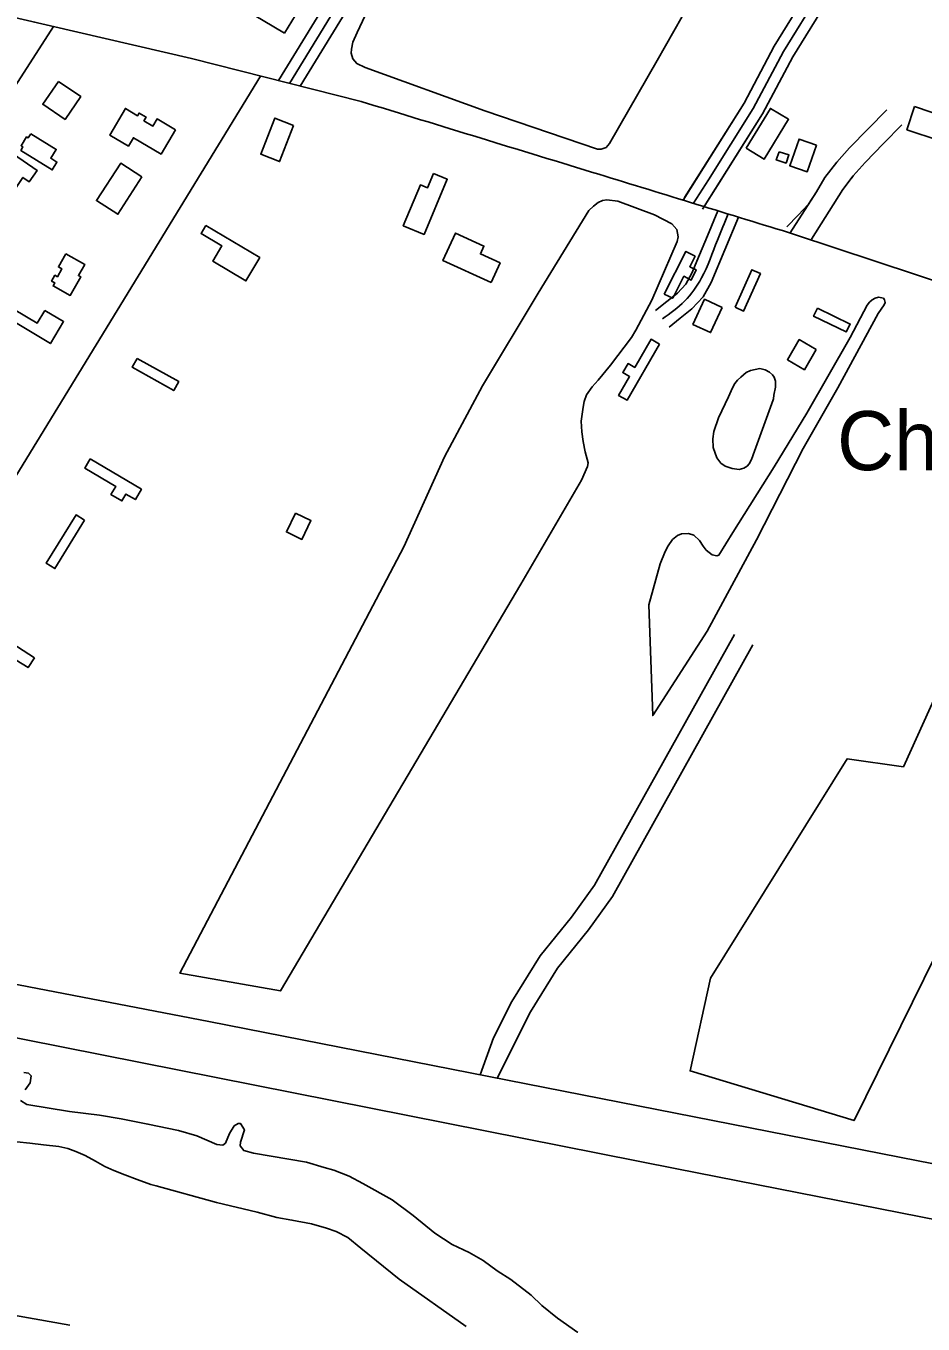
# Model space of a CAD drawing. Extents: x 3855477 to 3893699, y 299188 to 325115.
# Drawn here: x 3865905 to 3867166, y 308321 to 310145 of the extents above; entities that cross this region are included whole.
import ezdxf

# ---------------------------------------------------------------- set-up
doc = ezdxf.new("R2010")
doc.units = 0
for name, color, linetype in [('V-BLDG-OTLN', 7, 'Continuous'), ('V-LEVE-TOET', 7, 'Continuous'), ('V-ROAD-CNTR', 7, 'Continuous'), ('V-SITE-OTLN-IDEN', 7, 'Continuous'), ('V-SITE-VEGE', 7, 'Continuous'), ('V-TOPO-SHOR', 7, 'Continuous')]:
    doc.layers.add(name, color=color, linetype=linetype)

msp = doc.modelspace()

# ---------------------------------------------------------------- linework, layer by layer
at = {"layer": 'V-BLDG-OTLN'}
for points in [[(3866269.1, 310134.6), (3866211.3, 310168.9), (3866230.3, 310200.8), (3866253.5, 310187), (3866249.8, 310180.7), (3866284.3, 310160.2)], [(3865951.1, 310067), (3865982.5, 310045.7), (3865960.6, 310013.5), (3865929.2, 310034.8)], [(3866115.6, 309999.1), (3866095.5, 309964.9), (3866056.6, 309987.8), (3866049.6, 309976), (3866023.2, 309991.6), (3866045.2, 310028.9), (3866062.4, 310018.8), (3866064.5, 310022.5), (3866074.3, 310016.7), (3866071.3, 310011.7), (3866084, 310004.2), (3866089.9, 310014.3)], [(3866917.8, 309973), (3866952, 310029.1), (3866977.4, 310013.7), (3866943.1, 309957.5)], [(3867154.5, 310031.6), (3867199.9, 310016.4), (3867189, 309984), (3867143.7, 309999.1)], [(3866281.4, 310005.1), (3866261.9, 309954.3), (3866235.5, 309964.5), (3866255.1, 310015.3)], [(3865912.3, 309993.5), (3865948, 309971.3), (3865940.3, 309958.9), (3865949.1, 309953.5), (3865942.4, 309942.7), (3865898.3, 309970), (3865901.3, 309974.9), (3865898.7, 309976.5), (3865906.4, 309988.9), (3865908.6, 309987.6)], [(3867016.7, 309977.4), (3867003.6, 309939.9), (3866979, 309948.5), (3866992.1, 309985.9)], [(3865888.2, 309964.5), (3865921.2, 309942), (3865910.2, 309925.9), (3865901.2, 309932), (3865889.7, 309915.1), (3865865.7, 309931.5)], [(3866964, 309968.1), (3866977.8, 309963.6), (3866974, 309952.1), (3866960.2, 309956.6)], [(3866068.6, 309932.8), (3866034.8, 309880.2), (3866004.6, 309899.6), (3866038.8, 309952)], [(3866478.4, 309937.6), (3866497.7, 309929.5), (3866465, 309851.9), (3866435.9, 309864.2), (3866460, 309921.5), (3866469.8, 309917.3)], [(3866158.4, 309864.5), (3866234.2, 309819.4), (3866214.7, 309786.6), (3866168.2, 309814.3), (3866181, 309835.7), (3866151.7, 309853.2)], [(3866559.3, 309784.4), (3866491.6, 309815.3), (3866509.2, 309853.9), (3866549.3, 309835.6), (3866544.3, 309824.6), (3866571.9, 309812)], [(3865961.4, 309824.9), (3865988.1, 309809.9), (3865979.3, 309794.1), (3865982.4, 309792.4), (3865967.7, 309766.2), (3865943.7, 309779.6), (3865946.1, 309783.9), (3865941.6, 309786.5), (3865946.1, 309794.6), (3865949.7, 309792.6), (3865955.9, 309803.7), (3865951.1, 309806.4)], [(3866802.7, 309768.2), (3866833.1, 309828), (3866846.1, 309821.3), (3866838.6, 309806.6), (3866847.7, 309802), (3866840.6, 309787.9), (3866830.3, 309793.2), (3866814.6, 309762.2)], [(3866902.2, 309749.7), (3866925.7, 309802.4), (3866937.9, 309797), (3866914.3, 309744.2)], [(3866884, 309749.5), (3866867.8, 309714.1), (3866843, 309725.4), (3866859.3, 309760.8)], [(3865932, 309745.3), (3865958.3, 309729.6), (3865939.9, 309698.7), (3865881.2, 309733.7), (3865888.9, 309746.5), (3865921.2, 309727.2)], [(3867018, 309748.3), (3867064, 309726.1), (3867058.6, 309714.9), (3867012.6, 309737.1)], [(3866796, 309697.9), (3866750.4, 309618.9), (3866738.6, 309625.7), (3866753.9, 309652.3), (3866744.4, 309657.8), (3866751.8, 309670.6), (3866761.2, 309665.1), (3866784.1, 309704.7)], [(3867016.2, 309690.2), (3866999.6, 309661.9), (3866975.8, 309675.9), (3866992.4, 309704.2)], [(3866061.8, 309677.8), (3866120.3, 309645.1), (3866113.3, 309632.6), (3866054.8, 309665.3)], [(3865995.7, 309536.6), (3866067.9, 309493.9), (3866059.3, 309479.3), (3866046.1, 309487.1), (3866040.4, 309477.5), (3866025, 309486.6), (3866031.7, 309497.9), (3865988.1, 309523.7)], [(3866284.2, 309460.3), (3866271.5, 309433.9), (3866293.3, 309423.5), (3866306, 309449.9)], [(3865987.8, 309450.4), (3865946.1, 309382.5), (3865934.1, 309389.9), (3865975.9, 309457.8)], [(3865917.3, 309257.2), (3865862.5, 309292), (3865854.1, 309278.8), (3865879.1, 309262.9), (3865872.4, 309252.3), (3865885.5, 309244), (3865891.8, 309253.9), (3865908.5, 309243.3)]]:
    msp.add_lwpolyline(points, close=True, dxfattribs=at)
at = {"layer": 'V-LEVE-TOET'}
msp.add_lwpolyline([(3865816.5, 308346.2), (3865967, 308319.4)], dxfattribs=at)
at = {"layer": 'V-ROAD-CNTR'}
for points in [[(3866703.7, 310794), (3866565.5, 310565.8), (3866260.5, 310068.1)], [(3866716.6, 310786.2), (3866578.3, 310558), (3866275.7, 310064.2)], [(3866729.4, 310778.5), (3866591.1, 310550.2), (3866290.9, 310060.4)], [(3864154.9, 310565.8), (3864820.2, 310410.7), (3865696.9, 310201.7), (3866138.4, 310098.9), (3866376.7, 310038.7)], [(3866829.2, 309900.1), (3866914.9, 310036.6), (3866957.4, 310116.3), (3867008.4, 310199.3), (3867046.6, 310270.2), (3867079.2, 310353.6), (3867100.3, 310400.3), (3867137.6, 310467.8)], [(3866831, 309903.8), (3866852.3, 309936.9), (3866914.9, 310036.6), (3866957.4, 310116.3), (3867008.4, 310199.3), (3867046.6, 310270.2), (3867079.2, 310353.6), (3867100.3, 310400.3), (3867137.6, 310467.8)], [(3866843.7, 309895.7), (3866865, 309928.8), (3866927.8, 310029), (3866970.4, 310108.9), (3867021.4, 310191.9), (3867060.2, 310263.9), (3867093, 310347.8), (3867113.7, 310393.6), (3867150.8, 310460.6)], [(3866856.3, 309887.6), (3866877.6, 309920.8), (3866940.8, 310021.5), (3866983.4, 310101.4), (3867034.4, 310184.4), (3867073.8, 310257.6), (3867106.8, 310341.9), (3867127.2, 310386.8), (3867163.9, 310453.3)], [(3866858.9, 309891), (3866940.8, 310021.5), (3866983.4, 310101.4), (3867034.4, 310184.4), (3867073.8, 310257.6), (3867106.8, 310341.9), (3867127.2, 310386.8), (3867163.9, 310453.3)], [(3865944, 310144.2), (3865650.3, 309687.9), (3865194.3, 308971), (3865175.1, 308936.2), (3865158.2, 308867.3)], [(3865487.5, 308802.7), (3865506.7, 308872.4), (3865527, 308916.8), (3865605.7, 309046.7), (3866235.2, 310074.5)], [(3866975.1, 309862.4), (3866990.8, 309878.9), (3867005.6, 309894.4), (3867016.9, 309911.8), (3867028.5, 309932.1), (3867045.3, 309953.6), (3867063, 309973.6), (3867089.3, 310000.5), (3867115.3, 310027.1)], [(3866979.5, 309854), (3867016.9, 309911.8), (3867028.5, 309932.1), (3867045.3, 309953.6), (3867063, 309973.6), (3867089.3, 310000.5), (3867115.3, 310027.1)], [(3867009.2, 309899.9), (3867016.9, 309911.8), (3867028.5, 309932.1), (3867045.3, 309953.6), (3867063, 309973.6), (3867089.3, 310000.5), (3867115.3, 310027.1)], [(3867009.8, 309845.2), (3867053.5, 309915.3), (3867068.4, 309934.5), (3867084.9, 309953.2), (3867110.7, 309979.5), (3867136.7, 310006.1)], [(3867066.2, 309931.6), (3867068.4, 309934.5), (3867084.9, 309953.2), (3867110.7, 309979.5), (3867136.7, 310006.1)], [(3866878.1, 309885.1), (3866863.5, 309849.8), (3866852.4, 309823.2), (3866841.6, 309797.4), (3866833, 309782.1), (3866821.1, 309769.5), (3866806.2, 309757.5), (3866790.6, 309744.9)], [(3866907.2, 309876.2), (3866868.6, 309784.2), (3866857.3, 309764.2), (3866841.5, 309747.4), (3866825.1, 309734.2), (3866809.4, 309721.6)], [(3866985.9, 309852), (3867729.6, 309606.1), (3868057.1, 309502.7)], [(3860983.7, 309748.8), (3862185, 309519.4), (3863555.5, 309254), (3864992.1, 308971.5), (3866162.7, 308746.1), (3867159.7, 308550.2), (3867954.5, 308395.7), (3868105, 308368.9)], [(3860884.4, 309700.6), (3862044.8, 309470.5), (3862858.2, 309310.5), (3864777.9, 308942), (3865687.7, 308763.4), (3866820.3, 308539.2), (3867789.8, 308348.3), (3868065.6, 308297.8)], [(3866544, 308671.2), (3866562.8, 308723.4), (3866588.4, 308774.2), (3866628.3, 308838.4), (3866672.2, 308892.9), (3866704.8, 308937.9), (3866901.2, 309289.8)], [(3866567.7, 308666.5), (3866614.6, 308759.5), (3866652.8, 308821), (3866696, 308874.7), (3866730.1, 308921.8), (3866927.4, 309275.1)]]:
    msp.add_lwpolyline(points, dxfattribs=at)
for points in [[(3866376.7, 310038.7), (3866710.8, 309936.4), (3866985.9, 309852)], [(3866892.5, 309880.7), (3866877.4, 309844.1), (3866855.1, 309790.8), (3866831.3, 309758.4), (3866800, 309733.2)]]:
    msp.add_spline(points, degree=3, dxfattribs=at)
at = {"layer": 'V-SITE-VEGE'}
msp.add_lwpolyline([(3866886.5, 310261.7), (3866792.7, 310096.2), (3866725.7, 309979.9), (3866720.8, 309974), (3866714.2, 309971.6), (3866708.9, 309971.7), (3866550.6, 310025.5), (3866382.3, 310086.5), (3866370.4, 310092), (3866365.1, 310098.7), (3866362.8, 310106.4), (3866362.9, 310112.4), (3866364.8, 310121.9), (3866370.9, 310135.6), (3866419.9, 310239.6)], dxfattribs=at)
for points in [[(3866601, 309360.8), (3866263.5, 308789), (3866122, 308813.8), (3866436.7, 309412.8), (3866493.7, 309539.4), (3866547.4, 309639.1), (3866625.3, 309769.6), (3866696.5, 309885.8), (3866703.2, 309891.7), (3866709.8, 309897), (3866715.8, 309899.4), (3866721.8, 309900.5), (3866737.3, 309898.5), (3866789, 309879.4), (3866813.4, 309866.6), (3866820.4, 309858.8), (3866822.1, 309848.6), (3866820.8, 309842), (3866785.3, 309759.4), (3866762.7, 309717.3), (3866756.6, 309707.2), (3866726.9, 309668.1), (3866709.9, 309647.4), (3866701.5, 309638), (3866693.6, 309626.7), (3866689.9, 309617.2), (3866688.6, 309609.4), (3866686, 309589.8), (3866687, 309574.8), (3866688.6, 309561.1), (3866691.5, 309546.7), (3866695.5, 309531.1), (3866694.8, 309525.8), (3866686.2, 309506.7)], [(3866863, 309294.5), (3866786.4, 309175.9), (3866781.1, 309331.5), (3866796.8, 309389), (3866804.1, 309406.3), (3866808.2, 309414.2), (3866814.2, 309423.2), (3866821.4, 309429.1), (3866827, 309431.4), (3866836.9, 309431.7), (3866844.3, 309429.2), (3866852.2, 309422), (3866857.6, 309414), (3866861.5, 309408.4), (3866870.1, 309402), (3866876.8, 309400.4), (3866879.2, 309401.5), (3866899, 309433.3), (3866957, 309525.6), (3867002.9, 309601), (3867063.8, 309707.1), (3867087.7, 309752.7), (3867091.3, 309757), (3867094.9, 309760.1), (3867099.3, 309762.5), (3867104, 309763.6), (3867110.7, 309762.3), (3867112.3, 309759.9), (3867113, 309756.4), (3867111.8, 309753.2), (3867103.4, 309740.7), (3867046.8, 309636.5), (3866998, 309551.2), (3866932.5, 309422.7)], [(3866955.7, 309619.4), (3866929.5, 309547.3), (3866925.4, 309535.5), (3866921.8, 309529.6), (3866919, 309526.4), (3866914.6, 309523.7), (3866907.9, 309521.8), (3866898, 309523.1), (3866888.2, 309526.4), (3866882.3, 309530.4), (3866876.4, 309538), (3866871.5, 309552.7), (3866870.8, 309564.6), (3866872.5, 309575.2), (3866879, 309594.1), (3866892.8, 309623.6), (3866898.5, 309636.6), (3866902.1, 309642.5), (3866905.8, 309647.2), (3866910.2, 309651.5), (3866917.7, 309657.8), (3866923.7, 309660.8), (3866937.2, 309663.5), (3866944.7, 309661.8), (3866950.6, 309658.6), (3866954.9, 309654.6), (3866957.2, 309651.4), (3866959.1, 309645.8), (3866959, 309637.5), (3866956.9, 309626.1), (3866956.1, 309620.9)], [(3867551.5, 309488.6), (3867597, 309459.3), (3867371.6, 308991.5), (3867266, 309005), (3867069.4, 308606.8), (3866839.1, 308676.6), (3866867.9, 308807), (3867059.8, 309115.2), (3867138.9, 309103.9), (3867268.4, 309389.6), (3867369.2, 309358.1), (3867402.8, 309448.1), (3867491.5, 309418.8)]]:
    msp.add_lwpolyline(points, close=True, dxfattribs=at)
at = {"layer": 'V-TOPO-SHOR'}
for points in [[(3865902.6, 308674.6), (3865909.2, 308673.4), (3865912.8, 308669.7), (3865911.5, 308660.1), (3865904.2, 308650)], [(3865898, 308635.1), (3865906.9, 308629.6), (3865966.8, 308619.9), (3866008.8, 308614.6), (3866039.3, 308609.5), (3866077, 308601.9), (3866120.1, 308593), (3866145.8, 308585.5), (3866173.9, 308573.2), (3866182.2, 308572.5), (3866185.9, 308575.4), (3866191.4, 308588.6), (3866198.2, 308599.3), (3866203.6, 308602.8)], [(3866203.6, 308602.8), (3866207.2, 308602.8), (3866212.5, 308593.7), (3866206.9, 308576.4), (3866206.8, 308571.6), (3866211.6, 308564.9), (3866225.3, 308561.2), (3866299.6, 308548.3), (3866324.7, 308540.8), (3866338.4, 308537.1), (3866359.9, 308529), (3866379, 308518.6), (3866420.1, 308495.4), (3866449.9, 308473.4), (3866480.2, 308448.5), (3866504.6, 308432.6), (3866528.5, 308421.5), (3866548.2, 308410.5), (3866567.8, 308395.9), (3866586.9, 308383.7), (3866615.4, 308361.7), (3866630.8, 308347.2), (3866652.8, 308329.5), (3866681.4, 308309.4)], [(3865892.5, 308577), (3865911.1, 308575), (3865930.3, 308572.9), (3865951.8, 308570.3), (3865964.4, 308567.8), (3865975.8, 308563.4), (3865988.9, 308557.9), (3866003.2, 308549.9), (3866016.3, 308542.6), (3866028.9, 308537), (3866044.4, 308530.8), (3866061.7, 308524), (3866080.8, 308517.2), (3866088.6, 308515.3), (3866173.5, 308491.6), (3866230.4, 308478.3), (3866257.9, 308470.8), (3866279.4, 308467), (3866307, 308461.9), (3866327.9, 308455.6), (3866341.6, 308451.3), (3866357.7, 308442.7), (3866376.2, 308427.5), (3866430.3, 308384.3), (3866524.3, 308317.8)]]:
    msp.add_lwpolyline(points, dxfattribs=at)

# ---------------------------------------------------------------- texts
at = {"layer": 'V-SITE-OTLN-IDEN'}
msp.add_text('Ch.', height=83, rotation=0, dxfattribs=at).set_placement((3867045.6, 309520.7))

doc.saveas('drawing.dxf')
